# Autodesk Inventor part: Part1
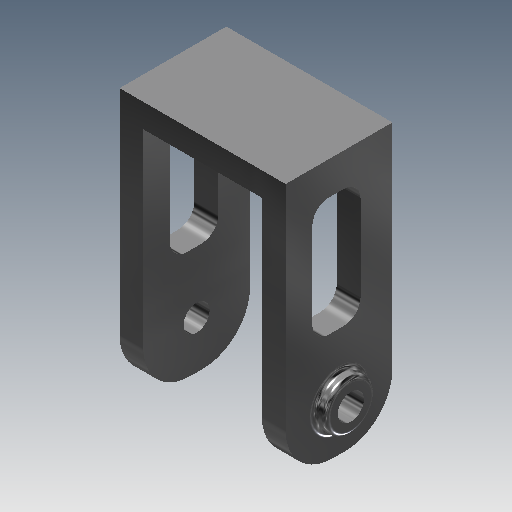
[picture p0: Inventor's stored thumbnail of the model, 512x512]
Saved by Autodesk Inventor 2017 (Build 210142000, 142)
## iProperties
Created: 2013-12
Part Number: Part1
Document SubType Name: Modeling
Designer: Paban Kumar Arjya
Density: 1 g/cm^3
Material: Generic
Appearance: Engine Turned
Author: Paban Kumar Arjya
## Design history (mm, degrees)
sketch "Sketch1"
  geometry: L1 (-18, -68.8)-(-18, 31.2); L2 (-18, 31.2)-(32, 31.2); L3 (32, 31.2)-(32, -68.8); L4 (42, -68.8)-(42, 41.2); L5 (42, 41.2)-(-28, 41.2); L6 (-28, 41.2)-(-28, -68.8); L7 (42, -68.8)-(32, -68.8); L8 (-18, -68.8)-(-28, -68.8); 1 further point
  constraints: 16 end point, 3 equal length, 3 perpendicular, 1 parallel, 1 vertical, 2 other
  dimensions: "d0" = 50 distance between parallel lines of L3 L1; "d1" = 100 distance of L1.start L1.end; "d2" = 10 distance between parallel lines of L6 L1
extrude "Extrusion1" new body sketch "Sketch1" distance "d3" = 45; taper "d4" = 0 deg
fillet "Fillet1" dims "d5" = 20
fillet "Fillet2" dims "d6" = 20
fillet "Fillet3" dims "d7" = 20
sketch "Sketch2"
  geometry: L1 (31.571, -14)-(11.208, -14); L2 (11.208, -14)-(11.208, -64); L3 (11.208, -64)-(31.571, -64); L4 (31.571, -64)-(31.571, -14); 1 further point
  constraints: 8 end point, 2 parallel, 1 horizontal, 1 perpendicular
extrude "Extrusion2" cut sketch "Sketch2" stored distance "d8" = 45; taper "d9" = 0 deg
fillet "Fillet4" dims "d10" = 7
fillet "Fillet5" dims "d11" = 7
fillet "Fillet6" dims "d12" = 7
fillet "Fillet7" dims "d13" = 7
sketch "Sketch5"
  geometry: L1 (11.208, -57)-(11.208, -21) reference; L2 (18.208, -14)-(24.571, -14) reference; L3 (31.571, -21)-(31.571, -57) reference; L4 (24.571, -64)-(18.208, -64) reference; L5 (45, -90)-(45, 0) reference; L6 (45, 0)-(0, 0) reference; L7 (0, 0)-(0, -90) reference; L8 (25, -110)-(20, -110) reference; A1 r 7 centre (18.208, -21) between (18.208, -14) and (11.208, -21) reference; A2 r 7 centre (24.571, -21) between (31.571, -21) and (24.571, -14) reference; A3 r 7 centre (24.571, -57) between (24.571, -64) and (31.571, -57) reference; A4 r 7 centre (18.208, -57) between (11.208, -57) and (18.208, -64) reference; A5 r 20 centre (25, -90) between (25, -110) and (45, -90) reference; A6 r 20 centre (20, -90) between (0, -90) and (20, -110) reference; 1 further point
sketch "Sketch6"
  geometry: C1 r 10.5 at (22.5, -90); 1 further point
  constraints: 1 centre point
  dimensions: "d20" = 21 diameter of C1
extrude "Extrusion5" join sketch "Sketch6" distance "d21" = 5; taper "d22" = 0 deg
fillet "Fillet9" dims "d23" = 2
fillet "Fillet10" dims "d24" = 2
sketch "Sketch7"
  geometry: C1 r 10.5 at (22.5, -90); 1 further point
  constraints: 1 centre point
  dimensions: "d25" = 21 diameter of C1
extrude "Extrusion6" join sketch "Sketch7" distance "d26" = 5; taper "d27" = 0 deg
fillet "Fillet11" dims "d28" = 2
sketch "Sketch8"
  geometry: C1 r 8.5 at (0, 0) reference; C2 r 5.5 at (0, 0); 1 further point
  constraints: 1 centre point, 1 coincident
  dimensions: "d29" = 11 diameter of C2
extrude "Extrusion7" cut sketch "Sketch8" stored distance "d30" = 5; taper "d31" = 0 deg
body "Solid1"
